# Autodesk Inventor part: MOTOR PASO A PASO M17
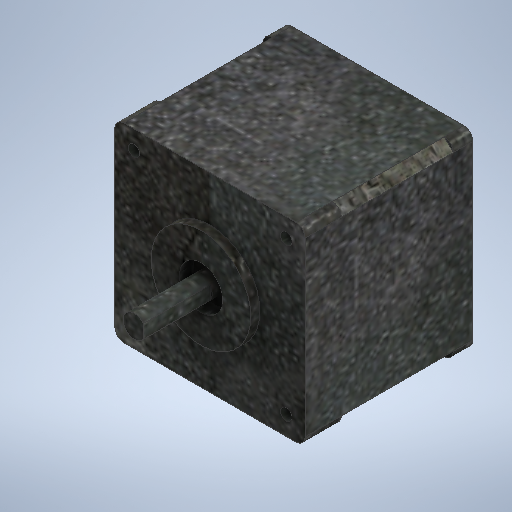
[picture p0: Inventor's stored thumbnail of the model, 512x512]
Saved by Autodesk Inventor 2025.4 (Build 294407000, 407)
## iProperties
Created: 2026-04
Part Number: MOTOR PASO A PASO M17
Material: Steel
Document SubType Name: Modeling
Designer: PC
Density: 7.85 g/cm^3
Appearance: Plate
Author: PC
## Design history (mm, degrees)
sketch "Sketch1"
  geometry: L1 (21, -21)-(-21, -21); L2 (-21, -21)-(-21, 21); L3 (-21, 21)-(21, 21); L4 (21, 21)-(21, -21); L5 (21, -21)-(-21, 21); L6 (-21, -21)-(21, 21); 1 further point
  constraints: 12 end point, 2 midpoint, 2 parallel, 1 horizontal, 1 perpendicular
  dimensions: "d0" = 42 distance of L2.end L3.end; "d1" = 42 distance of L1.end L2.end
extrude "Extrusion1" new body sketch "Sketch1" distance "d2" = 37; taper "d3" = 0 deg
sketch "Sketch2"
  geometry: L1 (21, 21)-(-21, 21) reference; L2 (-21, 21)-(-21, -21) reference; L3 (21, -21)-(21, 21) reference; L4 (-21, -21)-(21, -21) reference; C1 r 11 at (0, 0); C2 r 1.25 at (-16.8, 16.8); C3 r 1.25 at (16.8, 16.8); C4 r 1.25 at (16.8, -16.8); C5 r 1.25 at (-16.8, -16.8); 1 further point
  constraints: 5 centre point, 1 coincident
  dimensions: "d4" = 22 diameter of C1; "d5" = 2.5 diameter of C2; "d6" = 2.5 diameter of C3; "d7" = 2.5 diameter of C4; "d8" = 2.5 diameter of C5; "d9" = 4.2 distance from line of L1 C2.centre; "d10" = 4.2 distance from line of C2.centre L2; "d11" = 4.2 distance from line of L1 C3.centre; "d12" = 4.2 distance from line of L3 C3.centre; "d13" = 4.2 distance from line of L2 C5.centre; "d14" = 4.2 distance from line of L4 C5.centre; "d15" = 4.2 distance from line of L4 C4.centre; "d16" = 4.2 distance from line of L3 C4.centre
extrude "Extrusion2" join sketch "Sketch2" distance "d17" = 2; taper "d18" = 0 deg
extrude "Extrusion3" cut sketch "Sketch2" distance "d19" = 2; taper "d20" = 0 deg
sketch "Sketch3"
  geometry: L1 (-2.5, 3.333)-(-2.5, -2.5); L2 (2, 3.892)-(2, -3.446); C1 r 4.75 at (0, 0); C2 r 2.5 at (0, 0); 3 further points
  constraints: 4 end point, 2 centre point, 2 coincident, 2 vertical, 1 tangent
  dimensions: "d21" = 9.5 diameter of C1; "d22" = 5 diameter of C2; "d23" = 4.5 distance between parallel lines of L2 L1
extrude "Extrusion4" cut sketch "Sketch3" distance "d24" = 3; taper "d25" = 0 deg
extrude "Extrusion5" join sketch "Sketch3" distance "d26" = 24.7; taper "d27" = 0 deg
workplane "Work Plane1"
sketch "Sketch4"
  geometry: L1 (-21, 21)-(-21, -21) reference; L2 (19, -21)-(-19, -21); L3 (-21, -19)-(-21, 19); L4 (-19, 21)-(19, 21); L5 (21, 19)-(21, -19); L6 (21, -21)-(-21, 21); L7 (-21, -21)-(21, 21); L8 (19, 21)-(21, 19); L9 (19, -21)-(21, -19); L10 (-21, -19)-(-19, -21); L11 (-21, 19)-(-19, 21); L12 (21, -21)-(-21, -21); L13 (-21, -21)-(-21, 21); L14 (-21, 21)-(21, 21); L15 (21, 21)-(21, -21); L16 (21, -21)-(-21, 21); L17 (-21, -21)-(21, 21); 10 further points
  constraints: 32 end point, 8 point on line, 4 midpoint, 4 parallel, 2 horizontal, 2 perpendicular
  dimensions: "d29" = 2 distance of L4.end L7.end; "d30" = 2 distance of L5.start L7.end (= d29); "d31" = 2 distance of L2.start L6.start (= d29); "d32" = 2 distance of L5.end L6.start (= d31); "d33" = 2 distance of L3.start L7.start (= d29); "d34" = 2 distance of L2.end L7.start (= d33); "d35" = 2 distance of L3.end L1.start (= d29); "d36" = 2 distance of L4.start L1.start (= d35)
extrude "Extrusion6" cut sketch "Sketch4" distance "d37" = 24.7; taper "d38" = 0 deg
fillet "Fillet1" dims "d39" = 2
sketch "Sketch6"
  geometry: C1 r 3.959 at (0, 0.555); 1 further point
  constraints: 1 centre point
extrude "Extrusion7" cut sketch "Sketch6" distance "d41" = 10; taper "d42" = 0 deg
sketch "Sketch7"
  geometry: 1 further point
body "Solid1"
other parameters: "d28" = -8
